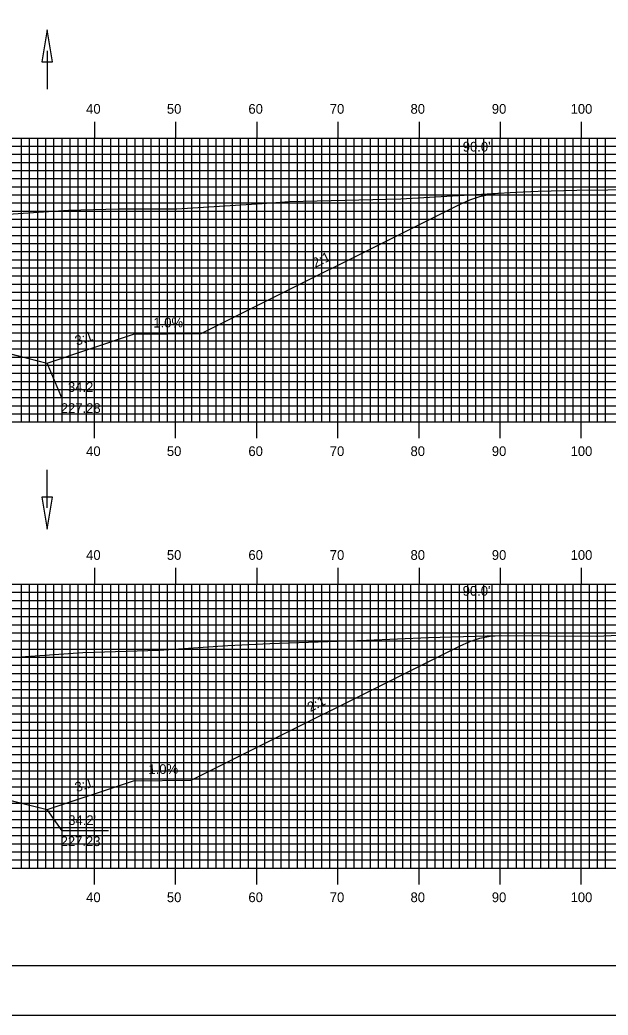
# Model space of a CAD drawing. Extents: x 1818063 to 1818407, y 442591 to 442811.
# Drawn here: x 1818259.9 to 1818332.4, y 442590.5 to 442713.2 of the extents above; entities that cross this region are included whole.
import ezdxf

# ---------------------------------------------------------------- set-up
doc = ezdxf.new("R2010")
doc.units = 0
for name, color, linetype in [('ANNOTATION', 7, 'Continuous'), ('BORDER', 7, 'Continuous'), ('D_Drainage_Ditch_Line', 7, 'Continuous'), ('D_Roadway_Centerline', 7, 'Continuous'), ('D_Roadway_SlopeLines', 7, 'Continuous'), ('D_Text_Standard', 7, 'Continuous'), ('H_V ANNOTATION', 7, 'Continuous'), ('MAJOR', 7, 'Continuous'), ('MINOR', 7, 'Continuous'), ('PLOT BOUNDARY', 7, 'Continuous'), ('S_Roadway_Centerline', 7, 'Continuous')]:
    doc.layers.add(name, color=color, linetype=linetype)

msp = doc.modelspace()

# ---------------------------------------------------------------- linework, layer by layer
at = {"layer": 'ANNOTATION'}
for points in [[(1818270.81, 442666.65), (1818265.12, 442666.65), (1818263.3, 442670.94)], [(1818270.85, 442613.25), (1818265.16, 442613.25), (1818263.3, 442615.9)]]:
    msp.add_lwpolyline(points, dxfattribs=at)
at = {"layer": 'BORDER'}
msp.add_lwpolyline([(1818079.53, 442596.67), (1818399.53, 442596.67), (1818399.53, 442806.67), (1818079.53, 442806.67)], close=True, dxfattribs=at)
at = {"layer": 'D_Drainage_Ditch_Line'}
for p, q in [((1818263.3, 442709.41), (1818263.3, 442704.71)), ((1818263.3, 442653.09), (1818263.3, 442657.79))]:
    msp.add_line(p, q, dxfattribs=at)
for points in [[(1818262.64, 442708.09), (1818263.96, 442708.09), (1818263.3, 442712.03)], [(1818263.96, 442654.4), (1818262.64, 442654.4), (1818263.3, 442650.47)]]:
    msp.add_lwpolyline(points, close=True, dxfattribs=at)
at = {"layer": 'D_Roadway_Centerline'}
for points in [[(1818139.13, 442678.51), (1818140.38, 442678.57), (1818141.63, 442678.43), (1818142.88, 442678.09), (1818144.13, 442677.57), (1818149.59, 442674.83), (1818184.32, 442674.49), (1818194.95, 442670.94), (1818198.95, 442671.94), (1818209.13, 442674.49), (1818217.13, 442674.81), (1818229.13, 442675.05), (1818241.13, 442674.81), (1818249.13, 442674.49), (1818259.3, 442671.94), (1818263.3, 442670.94), (1818273.93, 442674.49), (1818282.26, 442674.57), (1818314.13, 442690.5), (1818315.38, 442691.06), (1818316.63, 442691.48), (1818317.88, 442691.76), (1818319.13, 442691.9)], [(1818139.13, 442626.06), (1818140.38, 442626.12), (1818141.63, 442625.99), (1818142.88, 442625.65), (1818144.13, 442625.13), (1818154.91, 442619.73), (1818184.32, 442619.44), (1818194.95, 442615.9), (1818198.95, 442616.9), (1818209.13, 442619.44), (1818217.13, 442619.76), (1818229.13, 442620), (1818241.13, 442619.76), (1818249.13, 442619.44), (1818259.3, 442616.9), (1818263.3, 442615.9), (1818273.93, 442619.44), (1818281.06, 442619.51), (1818314.13, 442636.04), (1818315.38, 442636.59), (1818316.63, 442637), (1818317.88, 442637.25), (1818319.13, 442637.35)]]:
    msp.add_lwpolyline(points, dxfattribs=at)
at = {"layer": 'D_Roadway_SlopeLines'}
for points in [[(1818273.93, 442674.49), (1818282.26, 442674.57), (1818314.13, 442690.5), (1818315.38, 442691.06), (1818316.63, 442691.48), (1818317.88, 442691.76), (1818319.13, 442691.9)], [(1818249.13, 442674.49), (1818263.3, 442670.94)], [(1818263.3, 442670.94), (1818273.93, 442674.49)], [(1818273.93, 442619.44), (1818281.06, 442619.51), (1818314.13, 442636.04), (1818315.38, 442636.59), (1818316.63, 442637), (1818317.88, 442637.25), (1818319.13, 442637.35)], [(1818249.13, 442619.44), (1818263.3, 442615.9)], [(1818263.3, 442615.9), (1818273.93, 442619.44)]]:
    msp.add_lwpolyline(points, dxfattribs=at)
at = {"layer": 'MAJOR'}
for p, q in [((1818269.13, 442700.67), (1818269.13, 442698.67)), ((1818279.13, 442700.67), (1818279.13, 442698.67)), ((1818289.13, 442700.67), (1818289.13, 442698.67)), ((1818299.13, 442700.67), (1818299.13, 442698.67)), ((1818309.13, 442700.67), (1818309.13, 442698.67)), ((1818319.13, 442700.67), (1818319.13, 442698.67)), ((1818329.13, 442700.67), (1818329.13, 442698.67)), ((1818089.13, 442698.67), (1818369.13, 442698.67)), ((1818089.13, 442698.67), (1818369.13, 442698.67)), ((1818269.13, 442663.67), (1818269.13, 442698.67)), ((1818279.13, 442663.67), (1818279.13, 442698.67)), ((1818289.13, 442663.67), (1818289.13, 442698.67)), ((1818299.13, 442663.67), (1818299.13, 442698.67)), ((1818309.13, 442663.67), (1818309.13, 442698.67)), ((1818319.13, 442663.67), (1818319.13, 442698.67)), ((1818329.13, 442663.67), (1818329.13, 442698.67)), ((1818089.13, 442693.67), (1818369.13, 442693.67)), ((1818089.13, 442688.67), (1818369.13, 442688.67)), ((1818089.13, 442683.67), (1818369.13, 442683.67)), ((1818089.13, 442678.67), (1818369.13, 442678.67)), ((1818089.13, 442673.67), (1818369.13, 442673.67)), ((1818089.13, 442668.67), (1818369.13, 442668.67)), ((1818089.13, 442663.67), (1818369.13, 442663.67)), ((1818089.13, 442663.67), (1818369.13, 442663.67)), ((1818269.13, 442661.66), (1818269.13, 442663.67)), ((1818279.13, 442661.66), (1818279.13, 442663.67)), ((1818289.13, 442661.66), (1818289.13, 442663.67)), ((1818299.13, 442661.66), (1818299.13, 442663.67)), ((1818309.13, 442661.66), (1818309.13, 442663.67)), ((1818319.13, 442661.66), (1818319.13, 442663.67)), ((1818329.13, 442661.66), (1818329.13, 442663.67)), ((1818269.13, 442645.67), (1818269.13, 442643.67)), ((1818279.13, 442645.67), (1818279.13, 442643.67)), ((1818289.13, 442645.67), (1818289.13, 442643.67)), ((1818299.13, 442645.67), (1818299.13, 442643.67)), ((1818309.13, 442645.67), (1818309.13, 442643.67)), ((1818319.13, 442645.67), (1818319.13, 442643.67)), ((1818329.13, 442645.67), (1818329.13, 442643.67)), ((1818089.13, 442643.67), (1818369.13, 442643.67)), ((1818089.13, 442643.67), (1818369.13, 442643.67)), ((1818269.13, 442608.67), (1818269.13, 442643.67)), ((1818279.13, 442608.67), (1818279.13, 442643.67)), ((1818289.13, 442608.67), (1818289.13, 442643.67)), ((1818299.13, 442608.67), (1818299.13, 442643.67)), ((1818309.13, 442608.67), (1818309.13, 442643.67)), ((1818319.13, 442608.67), (1818319.13, 442643.67)), ((1818329.13, 442608.67), (1818329.13, 442643.67)), ((1818089.13, 442638.67), (1818369.13, 442638.67)), ((1818089.13, 442633.67), (1818369.13, 442633.67)), ((1818089.13, 442628.67), (1818369.13, 442628.67)), ((1818089.13, 442623.67), (1818369.13, 442623.67)), ((1818089.13, 442618.67), (1818369.13, 442618.67)), ((1818089.13, 442613.67), (1818369.13, 442613.67)), ((1818089.13, 442608.67), (1818369.13, 442608.67)), ((1818089.13, 442608.67), (1818369.13, 442608.67)), ((1818269.13, 442606.66), (1818269.13, 442608.67)), ((1818279.13, 442606.66), (1818279.13, 442608.67)), ((1818289.13, 442606.66), (1818289.13, 442608.67)), ((1818299.13, 442606.66), (1818299.13, 442608.67)), ((1818309.13, 442606.66), (1818309.13, 442608.67)), ((1818319.13, 442606.66), (1818319.13, 442608.67)), ((1818329.13, 442606.66), (1818329.13, 442608.67))]:
    msp.add_line(p, q, dxfattribs=at)
at = {"layer": 'MINOR'}
for p, q in [((1818260.13, 442663.67), (1818260.13, 442698.67)), ((1818261.13, 442663.67), (1818261.13, 442698.67)), ((1818262.13, 442663.67), (1818262.13, 442698.67)), ((1818263.13, 442663.67), (1818263.13, 442698.67)), ((1818264.13, 442663.67), (1818264.13, 442698.67)), ((1818265.13, 442663.67), (1818265.13, 442698.67)), ((1818266.13, 442663.67), (1818266.13, 442698.67)), ((1818267.13, 442663.67), (1818267.13, 442698.67)), ((1818268.13, 442663.67), (1818268.13, 442698.67)), ((1818270.13, 442663.67), (1818270.13, 442698.67)), ((1818271.13, 442663.67), (1818271.13, 442698.67)), ((1818272.13, 442663.67), (1818272.13, 442698.67)), ((1818273.13, 442663.67), (1818273.13, 442698.67)), ((1818274.13, 442663.67), (1818274.13, 442698.67)), ((1818275.13, 442663.67), (1818275.13, 442698.67)), ((1818276.13, 442663.67), (1818276.13, 442698.67)), ((1818277.13, 442663.67), (1818277.13, 442698.67)), ((1818278.13, 442663.67), (1818278.13, 442698.67)), ((1818280.13, 442663.67), (1818280.13, 442698.67)), ((1818281.13, 442663.67), (1818281.13, 442698.67)), ((1818282.13, 442663.67), (1818282.13, 442698.67)), ((1818283.13, 442663.67), (1818283.13, 442698.67)), ((1818284.13, 442663.67), (1818284.13, 442698.67)), ((1818285.13, 442663.67), (1818285.13, 442698.67)), ((1818286.13, 442663.67), (1818286.13, 442698.67)), ((1818287.13, 442663.67), (1818287.13, 442698.67)), ((1818288.13, 442663.67), (1818288.13, 442698.67)), ((1818290.13, 442663.67), (1818290.13, 442698.67)), ((1818291.13, 442663.67), (1818291.13, 442698.67)), ((1818292.13, 442663.67), (1818292.13, 442698.67)), ((1818293.13, 442663.67), (1818293.13, 442698.67)), ((1818294.13, 442663.67), (1818294.13, 442698.67)), ((1818295.13, 442663.67), (1818295.13, 442698.67)), ((1818296.13, 442663.67), (1818296.13, 442698.67)), ((1818297.13, 442663.67), (1818297.13, 442698.67)), ((1818298.13, 442663.67), (1818298.13, 442698.67)), ((1818300.13, 442663.67), (1818300.13, 442698.67)), ((1818301.13, 442663.67), (1818301.13, 442698.67)), ((1818302.13, 442663.67), (1818302.13, 442698.67)), ((1818303.13, 442663.67), (1818303.13, 442698.67)), ((1818304.13, 442663.67), (1818304.13, 442698.67)), ((1818305.13, 442663.67), (1818305.13, 442698.67)), ((1818306.13, 442663.67), (1818306.13, 442698.67)), ((1818307.13, 442663.67), (1818307.13, 442698.67)), ((1818308.13, 442663.67), (1818308.13, 442698.67)), ((1818310.13, 442663.67), (1818310.13, 442698.67)), ((1818311.13, 442663.67), (1818311.13, 442698.67)), ((1818312.13, 442663.67), (1818312.13, 442698.67)), ((1818313.13, 442663.67), (1818313.13, 442698.67)), ((1818314.13, 442663.67), (1818314.13, 442698.67)), ((1818315.13, 442663.67), (1818315.13, 442698.67)), ((1818316.13, 442663.67), (1818316.13, 442698.67)), ((1818317.13, 442663.67), (1818317.13, 442698.67)), ((1818318.13, 442663.67), (1818318.13, 442698.67)), ((1818320.13, 442663.67), (1818320.13, 442698.67)), ((1818321.13, 442663.67), (1818321.13, 442698.67)), ((1818322.13, 442663.67), (1818322.13, 442698.67)), ((1818323.13, 442663.67), (1818323.13, 442698.67)), ((1818324.13, 442663.67), (1818324.13, 442698.67)), ((1818325.13, 442663.67), (1818325.13, 442698.67)), ((1818326.13, 442663.67), (1818326.13, 442698.67)), ((1818327.13, 442663.67), (1818327.13, 442698.67)), ((1818328.13, 442663.67), (1818328.13, 442698.67)), ((1818330.13, 442663.67), (1818330.13, 442698.67)), ((1818331.13, 442663.67), (1818331.13, 442698.67)), ((1818332.13, 442663.67), (1818332.13, 442698.67)), ((1818089.13, 442697.67), (1818369.13, 442697.67)), ((1818089.13, 442696.67), (1818369.13, 442696.67)), ((1818089.13, 442695.67), (1818369.13, 442695.67)), ((1818089.13, 442694.67), (1818369.13, 442694.67)), ((1818089.13, 442692.67), (1818369.13, 442692.67)), ((1818089.13, 442691.67), (1818369.13, 442691.67)), ((1818089.13, 442690.67), (1818369.13, 442690.67)), ((1818089.13, 442689.67), (1818369.13, 442689.67)), ((1818089.13, 442687.67), (1818369.13, 442687.67)), ((1818089.13, 442686.67), (1818369.13, 442686.67)), ((1818089.13, 442685.67), (1818369.13, 442685.67)), ((1818089.13, 442684.67), (1818369.13, 442684.67)), ((1818089.13, 442682.67), (1818369.13, 442682.67)), ((1818089.13, 442681.67), (1818369.13, 442681.67)), ((1818089.13, 442680.67), (1818369.13, 442680.67)), ((1818089.13, 442679.67), (1818369.13, 442679.67)), ((1818089.13, 442677.67), (1818369.13, 442677.67)), ((1818089.13, 442676.67), (1818369.13, 442676.67)), ((1818089.13, 442675.67), (1818369.13, 442675.67)), ((1818089.13, 442674.67), (1818369.13, 442674.67)), ((1818089.13, 442672.67), (1818369.13, 442672.67)), ((1818089.13, 442671.67), (1818369.13, 442671.67)), ((1818089.13, 442670.67), (1818369.13, 442670.67)), ((1818089.13, 442669.67), (1818369.13, 442669.67)), ((1818089.13, 442667.67), (1818369.13, 442667.67)), ((1818089.13, 442666.67), (1818369.13, 442666.67)), ((1818089.13, 442665.67), (1818369.13, 442665.67)), ((1818089.13, 442664.67), (1818369.13, 442664.67)), ((1818089.13, 442642.67), (1818369.13, 442642.67)), ((1818260.13, 442608.67), (1818260.13, 442643.67)), ((1818261.13, 442608.67), (1818261.13, 442643.67)), ((1818262.13, 442608.67), (1818262.13, 442643.67)), ((1818263.13, 442608.67), (1818263.13, 442643.67)), ((1818264.13, 442608.67), (1818264.13, 442643.67)), ((1818265.13, 442608.67), (1818265.13, 442643.67)), ((1818266.13, 442608.67), (1818266.13, 442643.67)), ((1818267.13, 442608.67), (1818267.13, 442643.67)), ((1818268.13, 442608.67), (1818268.13, 442643.67)), ((1818270.13, 442608.67), (1818270.13, 442643.67)), ((1818271.13, 442608.67), (1818271.13, 442643.67)), ((1818272.13, 442608.67), (1818272.13, 442643.67)), ((1818273.13, 442608.67), (1818273.13, 442643.67)), ((1818274.13, 442608.67), (1818274.13, 442643.67)), ((1818275.13, 442608.67), (1818275.13, 442643.67)), ((1818276.13, 442608.67), (1818276.13, 442643.67)), ((1818277.13, 442608.67), (1818277.13, 442643.67)), ((1818278.13, 442608.67), (1818278.13, 442643.67)), ((1818280.13, 442608.67), (1818280.13, 442643.67)), ((1818281.13, 442608.67), (1818281.13, 442643.67)), ((1818282.13, 442608.67), (1818282.13, 442643.67)), ((1818283.13, 442608.67), (1818283.13, 442643.67)), ((1818284.13, 442608.67), (1818284.13, 442643.67)), ((1818285.13, 442608.67), (1818285.13, 442643.67)), ((1818286.13, 442608.67), (1818286.13, 442643.67)), ((1818287.13, 442608.67), (1818287.13, 442643.67)), ((1818288.13, 442608.67), (1818288.13, 442643.67)), ((1818290.13, 442608.67), (1818290.13, 442643.67)), ((1818291.13, 442608.67), (1818291.13, 442643.67)), ((1818292.13, 442608.67), (1818292.13, 442643.67)), ((1818293.13, 442608.67), (1818293.13, 442643.67)), ((1818294.13, 442608.67), (1818294.13, 442643.67)), ((1818295.13, 442608.67), (1818295.13, 442643.67)), ((1818296.13, 442608.67), (1818296.13, 442643.67)), ((1818297.13, 442608.67), (1818297.13, 442643.67)), ((1818298.13, 442608.67), (1818298.13, 442643.67)), ((1818300.13, 442608.67), (1818300.13, 442643.67)), ((1818301.13, 442608.67), (1818301.13, 442643.67)), ((1818302.13, 442608.67), (1818302.13, 442643.67)), ((1818303.13, 442608.67), (1818303.13, 442643.67)), ((1818304.13, 442608.67), (1818304.13, 442643.67)), ((1818305.13, 442608.67), (1818305.13, 442643.67)), ((1818306.13, 442608.67), (1818306.13, 442643.67)), ((1818307.13, 442608.67), (1818307.13, 442643.67)), ((1818308.13, 442608.67), (1818308.13, 442643.67)), ((1818310.13, 442608.67), (1818310.13, 442643.67)), ((1818311.13, 442608.67), (1818311.13, 442643.67)), ((1818312.13, 442608.67), (1818312.13, 442643.67)), ((1818313.13, 442608.67), (1818313.13, 442643.67)), ((1818314.13, 442608.67), (1818314.13, 442643.67)), ((1818315.13, 442608.67), (1818315.13, 442643.67)), ((1818316.13, 442608.67), (1818316.13, 442643.67)), ((1818317.13, 442608.67), (1818317.13, 442643.67)), ((1818318.13, 442608.67), (1818318.13, 442643.67)), ((1818320.13, 442608.67), (1818320.13, 442643.67)), ((1818321.13, 442608.67), (1818321.13, 442643.67)), ((1818322.13, 442608.67), (1818322.13, 442643.67)), ((1818323.13, 442608.67), (1818323.13, 442643.67)), ((1818324.13, 442608.67), (1818324.13, 442643.67)), ((1818325.13, 442608.67), (1818325.13, 442643.67)), ((1818326.13, 442608.67), (1818326.13, 442643.67)), ((1818327.13, 442608.67), (1818327.13, 442643.67)), ((1818328.13, 442608.67), (1818328.13, 442643.67)), ((1818330.13, 442608.67), (1818330.13, 442643.67)), ((1818331.13, 442608.67), (1818331.13, 442643.67)), ((1818332.13, 442608.67), (1818332.13, 442643.67)), ((1818089.13, 442641.67), (1818369.13, 442641.67)), ((1818089.13, 442640.67), (1818369.13, 442640.67)), ((1818089.13, 442639.67), (1818369.13, 442639.67)), ((1818089.13, 442637.67), (1818369.13, 442637.67)), ((1818089.13, 442636.67), (1818369.13, 442636.67)), ((1818089.13, 442635.67), (1818369.13, 442635.67)), ((1818089.13, 442634.67), (1818369.13, 442634.67)), ((1818089.13, 442632.67), (1818369.13, 442632.67)), ((1818089.13, 442631.67), (1818369.13, 442631.67)), ((1818089.13, 442630.67), (1818369.13, 442630.67)), ((1818089.13, 442629.67), (1818369.13, 442629.67)), ((1818089.13, 442627.67), (1818369.13, 442627.67)), ((1818089.13, 442626.67), (1818369.13, 442626.67)), ((1818089.13, 442625.67), (1818369.13, 442625.67)), ((1818089.13, 442624.67), (1818369.13, 442624.67)), ((1818089.13, 442622.67), (1818369.13, 442622.67)), ((1818089.13, 442621.67), (1818369.13, 442621.67)), ((1818089.13, 442620.67), (1818369.13, 442620.67)), ((1818089.13, 442619.67), (1818369.13, 442619.67)), ((1818089.13, 442617.67), (1818369.13, 442617.67)), ((1818089.13, 442616.67), (1818369.13, 442616.67)), ((1818089.13, 442615.67), (1818369.13, 442615.67)), ((1818089.13, 442614.67), (1818369.13, 442614.67)), ((1818089.13, 442612.67), (1818369.13, 442612.67)), ((1818089.13, 442611.67), (1818369.13, 442611.67)), ((1818089.13, 442610.67), (1818369.13, 442610.67)), ((1818089.13, 442609.67), (1818369.13, 442609.67))]:
    msp.add_line(p, q, dxfattribs=at)
at = {"layer": 'PLOT BOUNDARY'}
msp.add_lwpolyline([(1818063.34, 442590.55), (1818403.34, 442590.55), (1818403.34, 442810.55), (1818063.34, 442810.55)], close=True, dxfattribs=at)
at = {"layer": 'S_Roadway_Centerline'}
for points in [[(1818255.97, 442689.14), (1818265.92, 442689.77), (1818272.04, 442689.95), (1818279.28, 442689.96), (1818289.79, 442690.62), (1818293.13, 442690.84), (1818306.9, 442691.16), (1818321.08, 442692.02), (1818323.8, 442692.12), (1818328.59, 442692.26), (1818340.05, 442692.37), (1818347.43, 442692.61), (1818357.22, 442692.94), (1818368.5, 442693.27), (1818369.13, 442693.28)], [(1818254.12, 442634.29), (1818267.71, 442635.24), (1818277.04, 442635.55), (1818285.56, 442636.1), (1818290.76, 442636.35), (1818302.65, 442636.76), (1818310.29, 442637.08), (1818317.47, 442637.32), (1818319.29, 442637.36), (1818331.02, 442637.26), (1818336.48, 442637.5), (1818344.28, 442637.8), (1818352.85, 442637.69), (1818368.49, 442638.15), (1818369.13, 442638.16)]]:
    msp.add_lwpolyline(points, dxfattribs=at)

# ---------------------------------------------------------------- texts
at = {"layer": 'ANNOTATION'}
for s, rotation, p in [('2:1', 26.5651, (1818296.34, 442682.64)), ('1.0%', 0.5729, (1818276.39, 442675.31)), ('3:1', 18.4348, (1818266.95, 442673.07)), ('2:1', 26.5651, (1818295.74, 442627.89)), ('1.0%', 0.5729, (1818275.78, 442620.26)), ('3:1', 18.4348, (1818266.95, 442618.02))]:
    msp.add_text(s, height=1.2, rotation=rotation, dxfattribs=at).set_placement(p)
for s, p in [("34.2'", (1818265.86, 442667.38)), ('227.28', (1818264.98, 442664.78)), ("34.2'", (1818265.89, 442613.98)), ('227.23', (1818264.96, 442611.38))]:
    msp.add_text(s, height=1.2, dxfattribs=at).set_placement(p)
at = {"layer": 'D_Text_Standard'}
for p in [(1818314.52, 442697.01), (1818314.51, 442642.25)]:
    msp.add_text("90.0'", height=1.2, dxfattribs=at).set_placement(p)
at = {"layer": 'H_V ANNOTATION'}
for s, p in [('40', (1818268.1, 442701.67)), ('50', (1818278.05, 442701.67)), ('60', (1818288.1, 442701.67)), ('70', (1818298.13, 442701.67)), ('80', (1818308.08, 442701.67)), ('90', (1818318.1, 442701.67)), ('100', (1818327.81, 442701.67)), ('40', (1818268.1, 442659.47)), ('50', (1818278.05, 442659.47)), ('60', (1818288.1, 442659.47)), ('70', (1818298.13, 442659.47)), ('80', (1818308.08, 442659.47)), ('90', (1818318.1, 442659.47)), ('100', (1818327.81, 442659.47)), ('40', (1818268.1, 442646.67)), ('50', (1818278.05, 442646.67)), ('60', (1818288.1, 442646.67)), ('70', (1818298.13, 442646.67)), ('80', (1818308.08, 442646.67)), ('90', (1818318.1, 442646.67)), ('100', (1818327.81, 442646.67)), ('40', (1818268.1, 442604.47)), ('50', (1818278.05, 442604.47)), ('60', (1818288.1, 442604.47)), ('70', (1818298.13, 442604.47)), ('80', (1818308.08, 442604.47)), ('90', (1818318.1, 442604.47)), ('100', (1818327.81, 442604.47))]:
    msp.add_text(s, height=1.2, dxfattribs=at).set_placement(p)

doc.saveas('drawing.dxf')
